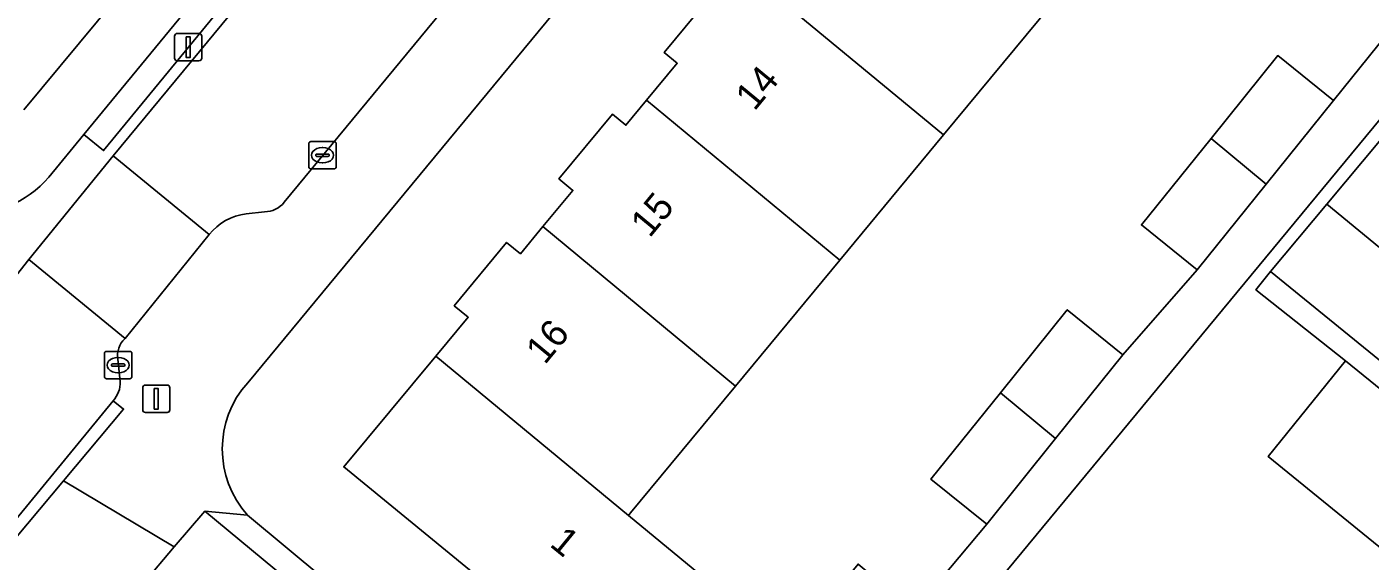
# Model space of a CAD drawing. Extents: x 162073 to 163043, y 381818 to 382561.
# Drawn here: x 162400.04 to 162449.04, y 382197.82 to 382217.31 of the extents above; entities that cross this region are included whole.
import ezdxf

# ---------------------------------------------------------------- set-up
doc = ezdxf.new("R2010")
doc.units = 0
for name, color, linetype in [('IMGEO_Erf', 7, 'Continuous'), ('IMGEO_Groenvoorziening', 7, 'Continuous'), ('IMGEO_Haag', 7, 'Continuous'), ('IMGEO_Kolk', 7, 'Continuous'), ('IMGEO_Lichtmast', 7, 'Continuous'), ('IMGEO_Pand', 7, 'Continuous'), ('IMGEO_Pand_nummerreeks', 7, 'Continuous'), ('IMGEO_Rijbaan_lokaal_open', 7, 'Continuous'), ('IMGEO_Voetpad_gesloten', 7, 'Continuous'), ('IMGEO_Voetpad_open', 7, 'Continuous')]:
    doc.layers.add(name, color=color, linetype=linetype)

msp = doc.modelspace()

# ---------------------------------------------------------------- linework, layer by layer
at = {"layer": 'IMGEO_Erf'}
for points in [[(162445.668, 382216.267), (162447.701, 382214.63), (162450.274, 382217.827), (162448.372, 382219.358), (162450.909, 382222.51), (162453.344, 382225.536), (162455.245, 382224.005), (162460.094, 382230.03), (162457.457, 382232.246), (162459.998, 382235.296), (162453.858, 382240.334), (162447.496, 382245.651)], [(162441.857, 382245.142), (162408.092, 382204.333)], [(162450.568, 382234.014), (162448.774, 382231.847), (162445.052, 382227.352), (162441.241, 382222.751), (162437.376, 382218.083), (162433.473, 382213.369), (162429.696, 382208.808), (162425.889, 382204.211), (162423.532, 382201.365), (162422.057, 382199.583), (162421.983, 382199.493), (162426.907, 382195.422)], [(162459.396, 382226.044), (162434.47, 382195.892), (162443.024, 382188.705), (162451.462, 382181.617)], [(162423.595, 382191.424), (162411.597, 382201.263), (162414.959, 382205.3), (162416.138, 382206.717), (162415.626, 382207.141), (162417.538, 382209.45), (162418.037, 382209.036), (162418.857, 382210.025), (162419.953, 382211.349), (162419.445, 382211.77), (162421.4, 382214.131), (162421.888, 382213.726), (162422.644, 382214.639), (162423.758, 382215.984), (162423.279, 382216.38), (162425.224, 382218.73)], [(162408.089, 382199.497), (162421.972, 382187.946), (162424.231, 382186.112), (162429.931, 382193.023), (162427.878, 382194.724), (162430.355, 382197.714), (162432.409, 382196.013), (162435.049, 382199.178), (162433.016, 382200.814), (162435.552, 382203.966), (162437.988, 382206.992), (162440.021, 382205.355), (162442.729, 382208.453), (162440.696, 382210.089), (162443.233, 382213.241), (162445.668, 382216.267)], [(162449.875, 382197.935), (162445.311, 382201.641), (162448.142, 382205.128), (162444.867, 382207.725), (162445.403, 382208.384), (162447.459, 382210.847), (162449.439, 382213.218)]]:
    msp.add_lwpolyline(points, dxfattribs=at)
msp.add_arc((162410.783, 382201.913), 3.619, 138.034, 221.8949, dxfattribs=at)
at = {"layer": 'IMGEO_Groenvoorziening'}
msp.add_lwpolyline([(162399.925, 382214.283), (162405.299, 382220.769), (162400.932, 382224.293), (162390.268, 382233.111), (162383.332, 382224.712), (162395.955, 382214.253)], dxfattribs=at)
msp.add_lwpolyline([(162402.113, 382213.38), (162402.831, 382212.8), (162412.361, 382224.396), (162411.657, 382224.982)], close=True, dxfattribs=at)
at = {"layer": 'IMGEO_Haag'}
msp.add_lwpolyline([(162402.113, 382213.38), (162402.831, 382212.8), (162412.361, 382224.396), (162411.657, 382224.982)], close=True, dxfattribs=at)
at = {"layer": 'IMGEO_Kolk'}
for p, q in [((162410.32, 382212.204), (162410.32, 382213.056)), ((162410.395, 382213.13), (162411.247, 382213.13)), ((162410.808, 382212.91), (162410.833, 382212.91)), ((162411.321, 382213.056), (162411.321, 382212.204)), ((162410.579, 382212.624), (162410.579, 382212.636)), ((162411.017, 382212.587), (162410.619, 382212.587)), ((162410.622, 382212.673), (162411.02, 382212.673)), ((162410.831, 382212.35), (162410.806, 382212.35)), ((162411.063, 382212.636), (162411.063, 382212.624)), ((162411.247, 382212.13), (162410.395, 382212.13)), ((162402.941, 382205.475), (162403.793, 382205.475)), ((162402.866, 382204.549), (162402.866, 382205.401)), ((162403.125, 382204.969), (162403.125, 382204.981)), ((162403.168, 382205.018), (162403.566, 382205.018)), ((162403.354, 382205.255), (162403.379, 382205.255)), ((162403.609, 382204.981), (162403.609, 382204.969)), ((162403.867, 382205.401), (162403.867, 382204.549)), ((162403.793, 382204.475), (162402.941, 382204.475)), ((162403.563, 382204.932), (162403.165, 382204.932)), ((162403.377, 382204.695), (162403.352, 382204.695))]:
    msp.add_line(p, q, dxfattribs=at)
for points in [[(162410.32, 382212.204), (162410.32, 382213.056)], [(162410.395, 382213.13), (162411.247, 382213.13)], [(162411.321, 382213.056), (162411.321, 382212.204)], [(162411.247, 382212.13), (162410.395, 382212.13)], [(162402.941, 382205.475), (162403.793, 382205.475)], [(162402.866, 382204.549), (162402.866, 382205.401)], [(162403.867, 382205.401), (162403.867, 382204.549)], [(162403.793, 382204.475), (162402.941, 382204.475)]]:
    msp.add_lwpolyline(points, dxfattribs=at)
for centre, radius, start, end in [((162410.397, 382213.054), 0.0765, 91.552, 178.448), ((162410.397, 382213.054), 0.0765, 91.552, 178.448), ((162411.245, 382213.054), 0.0765, 1.552, 88.448), ((162411.245, 382213.054), 0.0765, 1.552, 88.448), ((162410.619, 382212.633), 0.0403, 85.8775, 175.7526), ((162410.616, 382212.623), 0.0366, 178.938, 274.7102), ((162411.02, 382212.63), 0.043, 264.8664, 352.4533), ((162411.024, 382212.635), 0.0386, 1.7309, 96.639), ((162410.397, 382212.206), 0.0765, 181.552, 268.448), ((162410.397, 382212.206), 0.0765, 181.552, 268.448), ((162411.245, 382212.206), 0.0765, 271.552, 358.448), ((162411.245, 382212.206), 0.0765, 271.552, 358.448), ((162402.943, 382205.399), 0.0765, 91.552, 178.448), ((162402.943, 382205.399), 0.0765, 91.552, 178.448), ((162403.791, 382205.399), 0.0765, 1.552, 88.448), ((162403.791, 382205.399), 0.0765, 1.552, 88.448), ((162403.165, 382204.978), 0.0403, 85.8775, 175.7526), ((162403.162, 382204.968), 0.0366, 178.938, 274.7102), ((162403.566, 382204.975), 0.043, 264.8664, 352.4533), ((162403.57, 382204.98), 0.0386, 1.7309, 96.639), ((162402.943, 382204.551), 0.0765, 181.552, 268.448), ((162402.943, 382204.551), 0.0765, 181.552, 268.448), ((162403.791, 382204.551), 0.0765, 271.552, 358.448), ((162403.791, 382204.551), 0.0765, 271.552, 358.448)]:
    msp.add_arc(centre, radius, start, end, dxfattribs=at)
for centre, major_axis, ratio, start_param, end_param in [((162410.807, 382212.63), (-0.387, 0.002), 0.722429, 4.712389, 7.853982), ((162410.832, 382212.63), (-0.39, 0.002), 0.717154, 1.570796, 4.712389), ((162403.353, 382204.975), (-0.387, 0.002), 0.722429, 4.712389, 7.853982), ((162403.378, 382204.975), (-0.39, 0.002), 0.717154, 1.570796, 4.712389)]:
    msp.add_ellipse(centre, major_axis=major_axis, ratio=ratio, start_param=start_param, end_param=end_param, dxfattribs=at)
at = {"layer": 'IMGEO_Lichtmast'}
for p, q in [((162405.424, 382216.173), (162405.424, 382216.973)), ((162405.424, 382216.973), (162405.424, 382216.173)), ((162405.524, 382217.073), (162406.314, 382217.073)), ((162406.314, 382217.073), (162405.524, 382217.073)), ((162406.414, 382216.973), (162406.414, 382216.173)), ((162406.414, 382216.173), (162406.414, 382216.973)), ((162406.314, 382216.073), (162405.524, 382216.073)), ((162405.524, 382216.073), (162406.314, 382216.073)), ((162404.26, 382203.345), (162404.26, 382204.145)), ((162404.26, 382204.145), (162404.26, 382203.345)), ((162404.36, 382204.245), (162405.15, 382204.245)), ((162405.15, 382204.245), (162404.36, 382204.245)), ((162405.25, 382204.145), (162405.25, 382203.345)), ((162405.25, 382203.345), (162405.25, 382204.145)), ((162405.15, 382203.245), (162404.36, 382203.245)), ((162404.36, 382203.245), (162405.15, 382203.245))]:
    msp.add_line(p, q, dxfattribs=at)
for points in [[(162405.844, 382216.948), (162405.994, 382216.948), (162405.994, 382216.198), (162405.844, 382216.198), (162405.844, 382216.948)], [(162404.68, 382204.12), (162404.83, 382204.12), (162404.83, 382203.37), (162404.68, 382203.37), (162404.68, 382204.12)]]:
    msp.add_lwpolyline(points, dxfattribs=at)
for centre, start, end in [((162405.524, 382216.973), 90, 180), ((162405.524, 382216.973), 90, 180), ((162406.314, 382216.973), 0, 90), ((162406.314, 382216.973), 360, 90), ((162405.524, 382216.173), 180, 270), ((162405.524, 382216.173), 180, 270), ((162406.314, 382216.173), 270, 0), ((162406.314, 382216.173), 270, 0), ((162404.36, 382204.145), 90, 180), ((162404.36, 382204.145), 90, 180), ((162405.15, 382204.145), 0, 90), ((162405.15, 382204.145), 360, 90), ((162404.36, 382203.345), 180, 270), ((162404.36, 382203.345), 180, 270), ((162405.15, 382203.345), 270, 0), ((162405.15, 382203.345), 270, 0)]:
    msp.add_arc(centre, 0.1, start, end, dxfattribs=at)
at = {"layer": 'IMGEO_Pand'}
for points in [[(162437.376, 382218.083), (162430.336, 382223.903), (162429.589, 382223.001), (162429.089, 382223.415), (162427.122, 382221.039), (162427.643, 382220.608), (162426.454, 382219.172), (162433.473, 382213.369)], [(162426.454, 382219.172), (162425.736, 382218.306), (162425.224, 382218.73), (162423.279, 382216.38), (162423.758, 382215.984), (162422.644, 382214.639), (162429.696, 382208.808), (162433.473, 382213.369)], [(162443.233, 382213.241), (162445.244, 382211.578), (162447.701, 382214.63), (162445.668, 382216.267)], [(162418.857, 382210.025), (162425.889, 382204.211), (162429.696, 382208.808), (162422.644, 382214.639), (162421.888, 382213.726), (162421.4, 382214.131), (162419.445, 382211.77), (162419.953, 382211.349)], [(162443.233, 382213.241), (162440.696, 382210.089), (162442.729, 382208.453), (162445.244, 382211.578)], [(162449.439, 382213.218), (162447.459, 382210.847), (162455.833, 382203.951), (162457.82, 382206.316)], [(162453.812, 382201.546), (162455.833, 382203.951), (162447.459, 382210.847), (162445.403, 382208.384)], [(162425.889, 382204.211), (162418.857, 382210.025), (162418.037, 382209.036), (162417.538, 382209.45), (162415.626, 382207.141), (162416.138, 382206.717), (162414.959, 382205.3), (162421.983, 382199.493), (162422.057, 382199.583), (162423.532, 382201.365)], [(162437.564, 382202.303), (162440.021, 382205.355), (162437.988, 382206.992), (162435.552, 382203.966)], [(162421.983, 382199.493), (162414.959, 382205.3), (162411.597, 382201.263), (162423.595, 382191.424), (162426.785, 382195.275), (162426.907, 382195.422)], [(162452.706, 382201.422), (162448.142, 382205.128), (162445.311, 382201.641), (162449.875, 382197.935)], [(162437.564, 382202.303), (162435.552, 382203.966), (162433.016, 382200.814), (162435.049, 382199.178)]]:
    msp.add_lwpolyline(points, close=True, dxfattribs=at)
at = {"layer": 'IMGEO_Rijbaan_lokaal_open'}
for points in [[(162436.767, 382253.204), (162403.183, 382212.607)], [(162409.427, 382210.917), (162441.305, 382249.499)], [(162403.183, 382212.607), (162406.685, 382209.734)], [(162408.032, 382210.488), (162408.707, 382210.567)], [(162403.616, 382205.939), (162400.109, 382208.829), (162398.977, 382207.405), (162394.607, 382201.927), (162393.345, 382200.337), (162392.521, 382199.353), (162391.67, 382198.337), (162391.469, 382198.07), (162387.133, 382192.747), (162382.421, 382186.948), (162380.42, 382184.465), (162375.549, 382178.578), (162374.573, 382177.417), (162370.999, 382173.141), (162375.161, 382169.721), (162388.281, 382185.55), (162395.883, 382194.813), (162396.623, 382195.74), (162397.535, 382196.883), (162398.84, 382198.394), (162403.183, 382203.671)], [(162403.439, 382204.375), (162403.357, 382205.188)], [(162404.286, 382196.14), (162417.674, 382184.663), (162420.494, 382188.067), (162406.528, 382199.641), (162405.413, 382198.34), (162404.297, 382197.038), (162404.356, 382196.907)]]:
    msp.add_lwpolyline(points, dxfattribs=at)
msp.add_lwpolyline([(162403.183, 382212.607), (162400.109, 382208.829), (162403.616, 382205.939), (162406.685, 382209.734)], close=True, dxfattribs=at)
for centre, radius, start, end in [((162408.716, 382211.463), 0.896, 269.393, 322.4568), ((162408.253, 382208.513), 1.987, 96.3801, 142.0969), ((162404.152, 382205.334), 0.808, 131.5284, 190.4157), ((162402.459, 382204.333), 0.981, 317.568, 2.4658)]:
    msp.add_arc(centre, radius, start, end, dxfattribs=at)
at = {"layer": 'IMGEO_Voetpad_gesloten'}
for points in [[(162432.056, 382253.378), (162429.318, 382250), (162424.079, 382243.537), (162415.408, 382233.07), (162413.858, 382231.184), (162405.299, 382220.769), (162399.925, 382214.283)], [(162400.833, 382211.833), (162402.113, 382213.38), (162411.657, 382224.982)]]:
    msp.add_lwpolyline(points, dxfattribs=at)
msp.add_arc((162398.044, 382214.169), 3.638, 262.6671, 320.0462, dxfattribs=at)
at = {"layer": 'IMGEO_Voetpad_open'}
for points in [[(162403.183, 382212.607), (162436.767, 382253.204), (162440.272, 382257.441)], [(162434.441, 382252.496), (162435.17, 382251.939), (162433.57, 382250), (162424.387, 382238.869), (162423.643, 382239.491), (162422.308, 382237.834), (162423.023, 382237.249), (162413.733, 382226.021), (162413.008, 382226.597), (162411.657, 382224.982), (162412.361, 382224.396), (162402.831, 382212.8), (162402.113, 382213.38), (162400.833, 382211.833)], [(162443.836, 382252.37), (162441.305, 382249.499), (162409.427, 382210.917)], [(162408.092, 382204.333), (162441.857, 382245.142)], [(162397.58, 382210.561), (162395.437, 382207.815), (162393.848, 382205.919), (162396.436, 382204.943), (162398.63, 382207.71), (162398.977, 382207.405), (162400.109, 382208.829), (162403.183, 382212.607)], [(162408.707, 382210.567), (162408.032, 382210.488)], [(162406.685, 382209.734), (162403.616, 382205.939)], [(162453.812, 382201.546), (162445.403, 382208.384), (162444.867, 382207.725), (162448.142, 382205.128), (162452.706, 382201.422)], [(162403.357, 382205.188), (162403.439, 382204.375)], [(162403.183, 382203.671), (162403.565, 382203.37), (162401.376, 382200.754), (162405.413, 382198.34), (162406.528, 382199.641), (162408.089, 382199.497)], [(162404.356, 382196.907), (162404.297, 382197.038), (162405.413, 382198.34), (162401.376, 382200.754), (162399.186, 382198.137), (162398.84, 382198.394), (162397.535, 382196.883), (162396.623, 382195.74), (162395.883, 382194.813)]]:
    msp.add_lwpolyline(points, dxfattribs=at)
for points in [[(162459.396, 382226.044), (162464.155, 382231.869), (162462.887, 382232.868), (162460.346, 382229.818), (162460.094, 382230.03), (162455.245, 382224.005), (162455.377, 382223.899), (162452.92, 382220.847), (162450.405, 382217.722), (162450.274, 382217.827), (162447.701, 382214.63), (162445.244, 382211.578), (162442.729, 382208.453), (162440.021, 382205.355), (162437.564, 382202.303), (162435.049, 382199.178), (162432.409, 382196.013), (162429.931, 382193.023), (162424.231, 382186.112), (162424.614, 382185.801), (162425.454, 382185.106), (162428.604, 382188.91), (162431.821, 382192.739), (162434.47, 382195.892)], [(162399.186, 382198.137), (162401.376, 382200.754), (162403.565, 382203.37), (162403.183, 382203.671), (162398.84, 382198.394)], [(162425.454, 382185.106), (162424.614, 382185.801), (162424.231, 382186.112), (162421.972, 382187.946), (162408.089, 382199.497), (162406.528, 382199.641), (162420.494, 382188.067), (162426.212, 382183.329), (162426.761, 382182.88), (162455.361, 382159.209), (162459.935, 382155.423), (162460.487, 382156.099)]]:
    msp.add_lwpolyline(points, close=True, dxfattribs=at)
for centre, radius, start, end in [((162398.044, 382214.169), 3.638, 262.6671, 320.0462), ((162408.716, 382211.463), 0.896, 269.393, 322.4568), ((162408.253, 382208.513), 1.987, 96.3801, 142.0969), ((162404.152, 382205.334), 0.808, 131.5284, 190.4157), ((162402.459, 382204.333), 0.981, 317.568, 2.4658), ((162410.783, 382201.913), 3.619, 138.034, 221.8949)]:
    msp.add_arc(centre, radius, start, end, dxfattribs=at)

# ---------------------------------------------------------------- texts
at = {"layer": 'IMGEO_Pand_nummerreeks'}
for s, rotation, p in [('14', 50.4378, (162426.575, 382214.21)), ('15', 50.4378, (162422.752, 382209.584)), ('16', 50.4375, (162418.93, 382204.958)), ('1', 320.6493, (162419.069, 382198.395))]:
    msp.add_text(s, height=1, rotation=rotation, dxfattribs=at).set_placement(p)

doc.saveas('drawing.dxf')
